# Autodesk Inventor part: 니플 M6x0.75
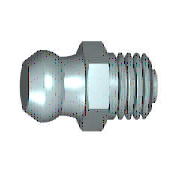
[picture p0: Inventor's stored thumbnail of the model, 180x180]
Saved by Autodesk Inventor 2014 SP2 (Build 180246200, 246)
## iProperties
IsCustomPart: 1
Created: 2012-02
Part Number: 니플 M6x0.75
Material: 강철, 연강
Description: 윤활 니플, 원추 유형 A
Document SubType Name: Modeling
Standard: JIS B 1575
Designer: mduedu
Standards Organization: JIS
Language: ko-KR
Size Designation: MT 6 x 0.75
Categories: <MemberInstance><Categories><Category DisplayName="기타 부품" InternalName="5aa15e00-363f-49f2-933f-16f664388e3f" Mnemonic="OTHER"><Category DisplayName="그리스 부속품" I
Density: 1 g/cm^3
Appearance: 강철
Author: mduedu
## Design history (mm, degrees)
sketch "스케치1"
  geometry: L1 (-8.8, 0)-(-8.8, 2.4); L2 (-8.8, 2.4)-(-7.335, 3.202); L3 (-8.8, 0)-(4.7, 0); L4 (4.7, 0)-(4.7, 1.5); L5 (4.7, 1.5)-(4, 1.5); L6 (4, 1.5)-(4, 3); L7 (4, 3)-(0, 3); L8 (-11.5, 0)-(7.4, 0) reference; L9 (0, -1.733)-(0, 10.398) reference; L10 (-3, 3.5)-(0, 3.5); L11 (0, 3.5)-(0, 3); A1 r 3.3 centre (-6.535, 0) between (-4.789, 2.8) and (-7.335, 3.202); A2 r 6 centre (-6.053, 8.665) between (-4.789, 2.8) and (-3, 3.5)
  constraints: 18 end point, 5 perpendicular, 4 point on circle, 2 centre point, 2 parallel, 2 point on line, 1 collinear, 1 vertical
  dimensions: "d0" = 13.5 distance between parallel lines of L1 L4 (= GL); "d1" = 5.6 diameter of A1.start L3 (= KGB2); "d2" = 0.7 distance between parallel lines of L4 L6 (= PHH); "d3" = 3 diameter of L5 L3 (= 0.5 x NND); "d4" = 6 diameter of L7 L3 (= NND); "d5" = 6.6 dimension on A1 L3 (= KR); "d6" = 4.8 diameter of L1.end L3 (= KGB1); "d7" = 6 radius of A2 (= RBN); "d11" = 7 diameter of L10.start L3 (= SW); "d14" = 3 distance of L10.start L10.end (= KOH); "d15" = 4 distance between parallel lines of L6 L11 (= NLG); "d61" = 7.33505 distance from line of L9 L2.end (computed from KGB1, KR, PHH, GL, NLG, VERS); "d62" = 6.53505 distance from line of L9 A1.centre (computed from NLG, GL, PHH, KR, KGB1)
revolve "본체" sketch "스케치1" stored, may be unused: angle "d25" = 90 deg
sketch "스케치2"
  geometry: L1 (2.021, 3.5)-(4.041, 0); L2 (4.041, 0)-(2.021, -3.5); L3 (2.021, -3.5)-(-2.021, -3.5); L4 (-2.021, -3.5)-(-4.041, 0); L5 (-4.041, 0)-(-2.021, 3.5); L6 (-2.021, 3.5)-(2.021, 3.5); C1 r 3.5 at (0, 0) reference; 1 further point
  constraints: 12 end point, 1 coincident, 1 horizontal, 1 tangent, 11 other
extrude "머리" join sketch "스케치2" distance "d17" = 3 (= KOH); taper "d18" = 0 deg
sketch "스케치3"
  geometry: L1 (2.687, 4.041)-(3, 4.041); L2 (3, 4.041)-(3, 3.5); L3 (3, 3.5)-(2.687, 4.041); L4 (0.313, 4.041)-(0, 4.041); L5 (0, 4.041)-(0, 3.5); L6 (0, 3.5)-(0.313, 4.041); L7 (3.6, 0)-(-0.6, 0) reference; L8 (0, 4.041)-(0, 2.021) reference; L9 (0, 4.041)-(3, 4.041) reference; L10 (3, 3.031)-(3, 4.041) reference
  constraints: 12 end point, 4 collinear, 3 perpendicular, 1 horizontal
  dimensions: "d19" = 3.5 distance from line of L5.end L7 (= 0.5 x SW); "d20" = 3.5 distance from line of L2.end L7 (= 0.5 x SW); "d21" = 30 deg angle of L6 L5; "d22" = 30 deg angle of L2 L3
revolve "모따기1" sketch "스케치3" stored, may be unused: angle "d56" = 90 deg
body "Solid1"
fillet "모깎기1" dims "d8" = 0.2 (= RR)
feature "스레드1" dims "d9" = 3.53991 (= NLG - GAL), "d10" = 0
chamfer "모따기2" distance "d23" = 0.46009 (= -0.5 x GD1 + 0.5 x NND); stored, may be unused: angle "d24" = 45 deg, second distance "d59" = 0.46009 (= -0.5 x GD1 + 0.5 x NND)
other parameters: "NLG" = 4 [user parameter; used in 4 equation terms], "GL" = 13.5 [user parameter; used in 3 equation terms], "NND" = 6 [user parameter; used in 4 equation terms], "KGB1" = 4.8 [user parameter; used in 3 equation terms], "KGB2" = 5.6 [user parameter; used in 1 equation term], "VERS" = 0.8 [user parameter; used in 1 equation term], "KR" = 6.6 [user parameter; used in 3 equation terms], "RBN" = 6 [user parameter; used in 1 equation term], "SW" = 7 [user parameter; used in 3 equation terms], "KOH" = 3 [user parameter; used in 2 equation terms], "GAL" = 0.46009 (= 0.61345 x PTC) [user parameter; used in 1 equation term], "FAWI" = 45 deg [user parameter], "PHH" = 0.7 [user parameter; used in 3 equation terms], "GD1" = 5.07983 (= THREADDIA - 1.2269 x PTC) [user parameter; used in 2 equation terms], "RR" = 0.2 [user parameter; used in 1 equation term], "d12" = 0, "d13" = 0, "GUL" = 0.46009 (= 0.61345 x PTC) [user parameter], "TPU" = 13.33333 (computed from PTC) [user parameter], "DULO" = 1.5 [user parameter], "PTC" = 0.75 [user parameter; used in 4 equation terms], "GEL" = 4 [user parameter], "THREADDIA" = 6 [user parameter; used in 1 equation term], "TOA" = 30 deg [user parameter]
